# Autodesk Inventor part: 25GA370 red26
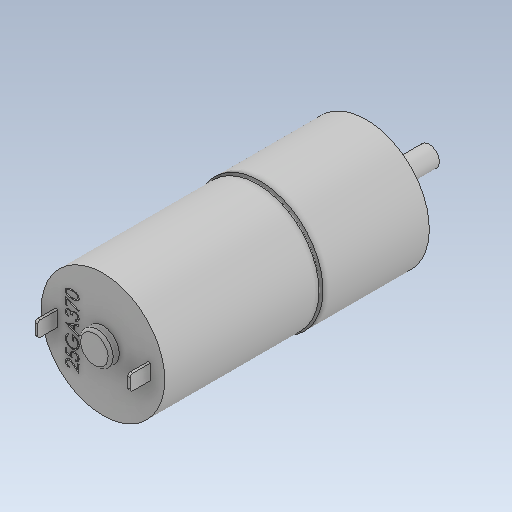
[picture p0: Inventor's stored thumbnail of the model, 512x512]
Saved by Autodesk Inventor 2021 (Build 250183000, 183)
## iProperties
Created: 2026-10
Part Number: 25GA370 red26
Material: Steel
Document SubType Name: Modeling
Designer: hp
Density: 7.85 g/cm^3
Appearance: Default
Author: hp
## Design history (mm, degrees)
feature "Body1"
body "Solid1"
